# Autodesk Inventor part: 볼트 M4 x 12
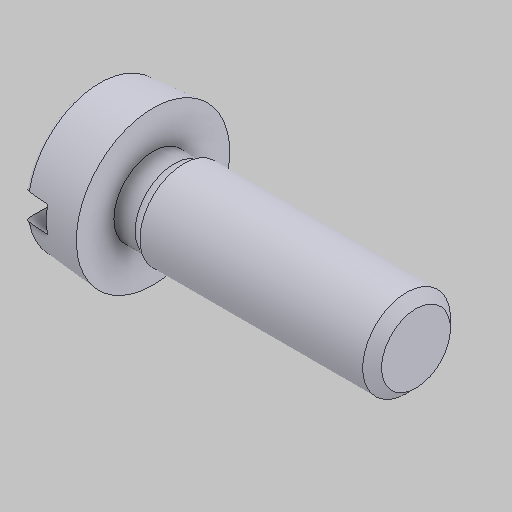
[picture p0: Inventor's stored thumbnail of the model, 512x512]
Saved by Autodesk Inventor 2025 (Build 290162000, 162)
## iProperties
Created: 2024-07
Part Number: 볼트 M4 x 12
Material: 강철, 연강
Description: 6각머리 태핑 나사
Document SubType Name: Modeling
Designer: 현기
Density: 7.85 g/cm^3
Appearance: 기본값
Author: jhkim
Sending System: Autodesk Inventor 2025
Preprocessor: ST-DEVELOPER v20
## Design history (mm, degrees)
feature "Solid1"
node "솔리드1"
